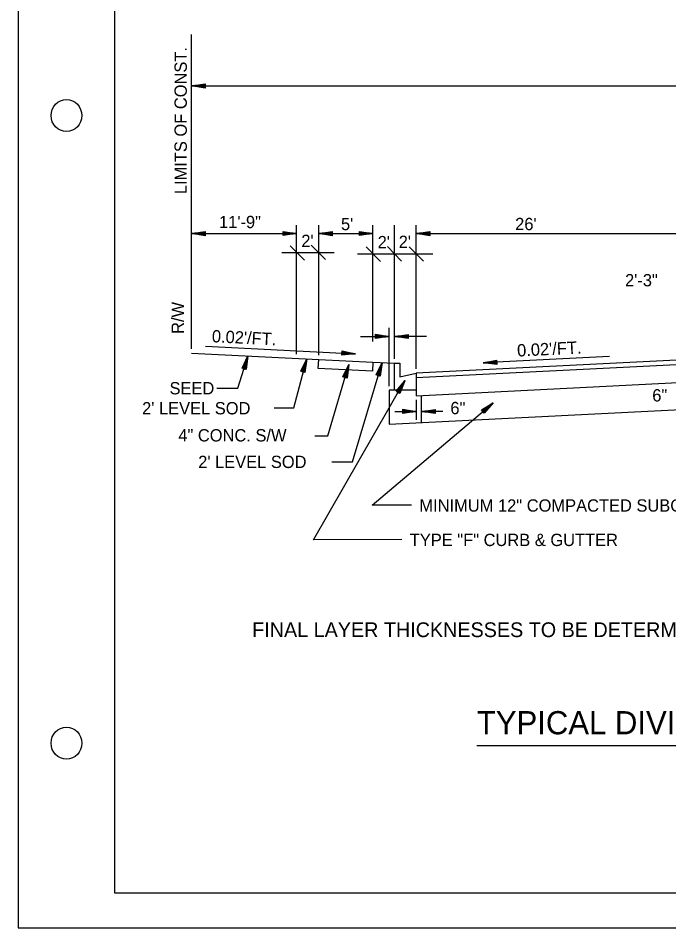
# Model space of a CAD drawing. Extents: x 29.7 to 46.4, y -39.2 to -28.2.
# Drawn here: x 29.7 to 34.11, y -39.2 to -33.04 of the extents above; entities that cross this region are included whole.
import ezdxf

# ---------------------------------------------------------------- set-up
doc = ezdxf.new("R2010")
doc.units = 0
for name, color, linetype in [('Level 1', 7, 'Continuous'), ('Level 10', 7, 'Continuous'), ('Level 4', 7, 'Continuous'), ('Level 60', 7, 'Continuous'), ('Level 8', 7, 'Continuous'), ('Level 9', 7, 'Continuous')]:
    doc.layers.add(name, color=color, linetype=linetype)

msp = doc.modelspace()

# ---------------------------------------------------------------- linework, layer by layer
at = {"layer": 'Level 4'}
msp.add_line((37.3605, -37.9659), (32.8081, -37.9659), dxfattribs=at)
at = {"layer": 'Level 60'}
for points in [[(29.7027, -39.1993), (46.0327, -39.1993), (46.0327, -28.1926), (29.7027, -28.1926)], [(30.3565, -28.4094), (45.7818, -28.4094), (45.7818, -38.965), (30.3565, -38.965)]]:
    msp.add_lwpolyline(points, close=True, dxfattribs=at)
for centre in [(30.0296, -33.6959), (30.0296, -37.9486)]:
    msp.add_ellipse(centre, major_axis=(0, 0.1083), ratio=0.96, dxfattribs=at)
at = {"layer": 'Level 8'}
for p, q in [((30.8765, -35.2762), (30.8765, -33.1461)), ((30.8765, -33.4948), (39.6765, -33.4948)), ((31.5884, -35.3118), (31.5884, -34.4376)), ((31.7381, -35.3193), (31.7381, -34.4376)), ((32.1048, -35.2277), (32.1048, -34.4376)), ((32.2515, -35.345), (32.2515, -34.4376)), ((32.3981, -35.4128), (32.3981, -34.4376)), ((30.8765, -34.4953), (31.5884, -34.4953)), ((31.7381, -34.4953), (32.1048, -34.4953)), ((32.3981, -34.4953), (34.3048, -34.4953)), ((31.6871, -34.5734), (31.7834, -34.6713)), ((31.4886, -34.6247), (31.842, -34.6247)), ((31.545, -34.5784), (31.6414, -34.6764)), ((31.9999, -34.6335), (32.5106, -34.6335)), ((32.0591, -34.5855), (32.1554, -34.6835)), ((32.2025, -34.5834), (32.2989, -34.6814)), ((32.3509, -34.5847), (32.4472, -34.6827)), ((32.0215, -35.1924), (32.2148, -35.1924)), ((32.2148, -35.5283), (32.2148, -35.1346)), ((32.4683, -35.1924), (32.2515, -35.1924)), ((30.8765, -35.3051), (31.7381, -35.3482)), ((30.9709, -35.2593), (31.9862, -35.31)), ((32.1048, -35.3665), (32.2515, -35.3739)), ((34.4331, -35.3399), (32.3981, -35.4417)), ((34.3048, -35.3776), (32.3981, -35.4729)), ((33.708, -35.3289), (32.8512, -35.3717)), ((32.3981, -35.6229), (32.3981, -35.7584)), ((32.4348, -35.7758), (32.4348, -35.5922)), ((32.2538, -35.7007), (32.3981, -35.7007)), ((32.5791, -35.7007), (32.4348, -35.7007))]:
    msp.add_line(p, q, dxfattribs=at)
for points in [[(31.0482, -35.5439), (31.1892, -35.5433), (31.2573, -35.328)], [(31.4367, -35.6762), (31.5703, -35.6762), (31.6572, -35.3441)], [(31.7381, -35.3482), (32.1048, -35.3665), (32.1018, -35.4269), (31.7351, -35.4086), (31.7381, -35.3482)], [(31.8256, -36.0421), (31.9668, -36.0421), (32.1675, -35.3698)], [(32.2515, -35.3739), (32.2881, -35.3739), (32.2881, -35.4655), (32.3981, -35.4417), (32.3981, -35.5572), (32.2515, -35.5572), (32.2515, -35.3739)], [(31.7107, -35.866), (31.8006, -35.866), (31.942, -35.3825)], [(32.2999, -36.5692), (31.7021, -36.5698), (32.3204, -35.4918)], [(32.2515, -35.5572), (32.2148, -35.5572), (32.2148, -35.7868), (34.5065, -35.6722), (34.5065, -35.4619), (34.4698, -35.4619)], [(32.3981, -35.5572), (32.3981, -35.594), (34.3048, -35.4987), (34.3048, -35.4619)], [(32.3669, -36.3359), (32.1005, -36.3359), (32.9194, -35.6418)]]:
    msp.add_lwpolyline(points, dxfattribs=at)
at = {"layer": 'Level 9'}
for p, q in [((30.968, -33.4856), (30.8765, -33.4948)), ((30.8765, -33.4948), (30.968, -33.4948)), ((30.968, -33.4994), (30.8765, -33.4948)), ((30.8765, -33.4948), (30.968, -33.5039)), ((30.968, -33.5094), (30.8766, -33.4945)), ((30.8769, -33.4942), (30.968, -33.4811)), ((30.968, -33.4902), (30.881, -33.4948)), ((30.968, -33.4811), (30.968, -33.5094)), ((30.968, -33.5039), (30.968, -33.4902)), ((30.968, -33.4948), (30.968, -33.4994)), ((30.968, -34.4862), (30.8765, -34.4953)), ((30.8765, -34.4953), (30.968, -34.4953)), ((30.968, -34.4999), (30.8765, -34.4953)), ((30.8765, -34.4953), (30.968, -34.5045)), ((30.968, -34.51), (30.8766, -34.4951)), ((30.8769, -34.4947), (30.968, -34.4816)), ((30.968, -34.4908), (30.881, -34.4953)), ((30.968, -34.4816), (30.968, -34.51)), ((30.968, -34.5045), (30.968, -34.4908)), ((30.968, -34.4953), (30.968, -34.4999)), ((31.4968, -34.509), (31.4968, -34.4807)), ((31.4968, -34.4807), (31.5883, -34.4956)), ((31.588, -34.4959), (31.4968, -34.509)), ((31.5884, -34.4953), (31.4969, -34.4862)), ((31.4969, -34.4862), (31.4969, -34.4999)), ((31.4969, -34.4953), (31.4969, -34.4908)), ((31.4969, -34.4908), (31.5884, -34.4953)), ((31.4969, -34.5045), (31.5884, -34.4953)), ((31.5884, -34.4953), (31.4969, -34.4953)), ((31.4969, -34.4999), (31.5838, -34.4953)), ((31.8296, -34.4862), (31.7381, -34.4953)), ((31.7381, -34.4953), (31.8296, -34.4953)), ((31.8296, -34.4999), (31.7381, -34.4953)), ((31.7381, -34.4953), (31.8296, -34.5045)), ((31.8297, -34.51), (31.7383, -34.4951)), ((31.7386, -34.4947), (31.8297, -34.4816)), ((31.8296, -34.4908), (31.7427, -34.4953)), ((31.8296, -34.5045), (31.8296, -34.4908)), ((31.8296, -34.4953), (31.8296, -34.4999)), ((31.8297, -34.4816), (31.8297, -34.51)), ((32.0132, -34.509), (32.0132, -34.4807)), ((32.0132, -34.4807), (32.1046, -34.4956)), ((32.1043, -34.4959), (32.0132, -34.509)), ((32.1048, -34.4953), (32.0133, -34.4862)), ((32.0133, -34.4862), (32.0133, -34.4999)), ((32.0133, -34.4953), (32.0133, -34.4908)), ((32.0133, -34.4908), (32.1048, -34.4953)), ((32.0133, -34.5045), (32.1048, -34.4953)), ((32.1048, -34.4953), (32.0133, -34.4953)), ((32.0133, -34.4999), (32.1002, -34.4953)), ((32.4896, -34.4862), (32.3981, -34.4953)), ((32.3981, -34.4953), (32.4896, -34.4953)), ((32.4896, -34.4999), (32.3981, -34.4953)), ((32.3981, -34.4953), (32.4896, -34.5045)), ((32.4897, -34.51), (32.3983, -34.4951)), ((32.3986, -34.4947), (32.4897, -34.4816)), ((32.4896, -34.4908), (32.4027, -34.4953)), ((32.4896, -34.5045), (32.4896, -34.4908)), ((32.4896, -34.4953), (32.4896, -34.4999)), ((32.4897, -34.4816), (32.4897, -34.51)), ((32.1232, -35.2061), (32.1232, -35.1777)), ((32.1232, -35.1777), (32.2146, -35.1926)), ((32.2148, -35.1924), (32.1233, -35.1832)), ((32.1233, -35.1832), (32.1233, -35.1969)), ((32.1233, -35.1924), (32.1233, -35.1878)), ((32.1233, -35.1878), (32.2148, -35.1924)), ((32.1233, -35.2015), (32.2148, -35.1924)), ((32.2148, -35.1924), (32.1233, -35.1924)), ((32.1233, -35.1969), (32.2102, -35.1924)), ((32.343, -35.1832), (32.2515, -35.1924)), ((32.2515, -35.1924), (32.343, -35.1924)), ((32.343, -35.1969), (32.2515, -35.1924)), ((32.2515, -35.1924), (32.343, -35.2015)), ((32.343, -35.207), (32.2516, -35.1921)), ((32.2519, -35.1918), (32.343, -35.1787)), ((32.343, -35.1878), (32.256, -35.1924)), ((32.343, -35.1787), (32.343, -35.207)), ((32.343, -35.2015), (32.343, -35.1878)), ((32.343, -35.1924), (32.343, -35.1969)), ((32.2143, -35.193), (32.1232, -35.2061)), ((31.8942, -35.3188), (31.8956, -35.2906)), ((31.9859, -35.3103), (31.8942, -35.3188)), ((31.8945, -35.3143), (31.9864, -35.3098)), ((31.8954, -35.2961), (31.8947, -35.3098)), ((31.8947, -35.3098), (31.9818, -35.3095)), ((31.895, -35.3052), (31.8952, -35.3006)), ((31.9864, -35.3098), (31.895, -35.3052)), ((31.8952, -35.3006), (31.9864, -35.3098)), ((31.9864, -35.3098), (31.8954, -35.2961)), ((31.8956, -35.2906), (31.9862, -35.31)), ((31.2185, -35.4082), (31.2585, -35.3246)), ((31.2583, -35.3244), (31.2238, -35.4097)), ((31.2282, -35.4109), (31.2583, -35.3244)), ((31.2583, -35.3244), (31.2326, -35.4122)), ((31.237, -35.4135), (31.257, -35.3288)), ((31.2414, -35.4148), (31.2583, -35.3244)), ((31.2587, -35.325), (31.2457, -35.4161)), ((31.6174, -35.4279), (31.6574, -35.3443)), ((31.6572, -35.3441), (31.6227, -35.4294)), ((31.6271, -35.4307), (31.6572, -35.3441)), ((31.6572, -35.3441), (31.6315, -35.4319)), ((31.6359, -35.4332), (31.6559, -35.3485)), ((31.6403, -35.4345), (31.6572, -35.3441)), ((31.6576, -35.3447), (31.6446, -35.4359)), ((32.1277, -35.4536), (32.1677, -35.37)), ((32.1675, -35.3698), (32.133, -35.455)), ((32.1374, -35.4563), (32.1675, -35.3698)), ((32.1675, -35.3698), (32.1418, -35.4576)), ((32.1462, -35.4589), (32.1662, -35.3742)), ((32.1506, -35.4602), (32.1675, -35.3698)), ((32.1679, -35.3704), (32.1549, -35.4615)), ((32.9421, -35.358), (32.8512, -35.3717)), ((32.8512, -35.3717), (32.9426, -35.3671)), ((32.9428, -35.3717), (32.8512, -35.3717)), ((32.8512, -35.3717), (32.9431, -35.3763)), ((32.9434, -35.3818), (32.8513, -35.3714)), ((32.8516, -35.3711), (32.942, -35.3535)), ((32.9424, -35.3626), (32.8558, -35.3715)), ((32.942, -35.3535), (32.9434, -35.3818)), ((32.9431, -35.3763), (32.9424, -35.3626)), ((32.9426, -35.3671), (32.9428, -35.3717)), ((31.2457, -35.4161), (31.2185, -35.4082)), ((31.2238, -35.4097), (31.237, -35.4135)), ((31.2326, -35.4122), (31.2282, -35.4109)), ((31.6446, -35.4359), (31.6174, -35.4279)), ((31.6227, -35.4294), (31.6359, -35.4332)), ((31.6315, -35.4319), (31.6271, -35.4307)), ((31.9022, -35.4663), (31.9422, -35.3827)), ((31.942, -35.3825), (31.9075, -35.4677)), ((31.9119, -35.469), (31.942, -35.3825)), ((31.942, -35.3825), (31.9163, -35.4703)), ((31.9207, -35.4716), (31.9407, -35.3869)), ((31.9251, -35.4729), (31.942, -35.3825)), ((31.9424, -35.3831), (31.9294, -35.4742)), ((31.9294, -35.4742), (31.9022, -35.4663)), ((31.9075, -35.4677), (31.9207, -35.4716)), ((31.9163, -35.4703), (31.9119, -35.469)), ((32.1549, -35.4615), (32.1277, -35.4536)), ((32.133, -35.455), (32.1462, -35.4589)), ((32.1418, -35.4576), (32.1374, -35.4563)), ((32.262, -35.5643), (32.32, -35.4921)), ((32.3199, -35.4918), (32.2669, -35.567)), ((32.2708, -35.5692), (32.3199, -35.4918)), ((32.3199, -35.4918), (32.2748, -35.5715)), ((32.2788, -35.5738), (32.3176, -35.4958)), ((32.2828, -35.576), (32.3199, -35.4918)), ((32.3202, -35.4925), (32.2867, -35.5783)), ((32.2867, -35.5783), (32.262, -35.5643)), ((32.2669, -35.567), (32.2788, -35.5738)), ((32.2748, -35.5715), (32.2708, -35.5692)), ((32.84, -35.6896), (32.9195, -35.6421)), ((32.9194, -35.6418), (32.8436, -35.6937)), ((32.8465, -35.6972), (32.9194, -35.6418)), ((32.9194, -35.6418), (32.8494, -35.7007)), ((32.8524, -35.7042), (32.9159, -35.6447)), ((32.8553, -35.7077), (32.9194, -35.6418)), ((32.9195, -35.6425), (32.8582, -35.7112)), ((32.3065, -35.7144), (32.3065, -35.6861)), ((32.3065, -35.6861), (32.398, -35.701)), ((32.3977, -35.7013), (32.3065, -35.7144)), ((32.3981, -35.7007), (32.3066, -35.6916)), ((32.3066, -35.6916), (32.3066, -35.7053)), ((32.3066, -35.7007), (32.3066, -35.6961)), ((32.3066, -35.6961), (32.3981, -35.7007)), ((32.3066, -35.7098), (32.3981, -35.7007)), ((32.3981, -35.7007), (32.3066, -35.7007)), ((32.3066, -35.7053), (32.3935, -35.7007)), ((32.5263, -35.6916), (32.4348, -35.7007)), ((32.4348, -35.7007), (32.5263, -35.7007)), ((32.5263, -35.7053), (32.4348, -35.7007)), ((32.4348, -35.7007), (32.5263, -35.7098)), ((32.5264, -35.7153), (32.4349, -35.7004)), ((32.4353, -35.7001), (32.5264, -35.687)), ((32.5263, -35.6961), (32.4394, -35.7007)), ((32.5263, -35.7098), (32.5263, -35.6961)), ((32.5263, -35.7007), (32.5263, -35.7053)), ((32.5264, -35.687), (32.5264, -35.7153)), ((32.8582, -35.7112), (32.84, -35.6896)), ((32.8436, -35.6937), (32.8524, -35.7042)), ((32.8494, -35.7007), (32.8465, -35.6972))]:
    msp.add_line(p, q, dxfattribs=at)

# ---------------------------------------------------------------- texts
at = {"layer": 'Level 1'}
msp.add_text('FINAL LAYER THICKNESSES TO BE DETERMINED BY THE ENGINEERS PAVEMENT DESIGN CALCULATIONS.', height=0.1, dxfattribs=at).set_placement((31.2874, -37.2297))
at = {"layer": 'Level 10'}
msp.add_text('TYPICAL DIVIDED ROADWAY SECTION', height=0.157302, dxfattribs=at).set_placement((32.8088, -37.8884))
at = {"layer": 'Level 8'}
for s, height, rotation, p in [('LIMITS OF CONST.', 0.083333, 90, (30.8446, -34.2283)), ('R/W', 0.08333, 90, (30.8246, -35.175)), ("0.02'/FT.", 0.08333, 357.13759, (31.0126, -35.2311)), ("0.02'/FT.", 0.08333, 2.86241, (33.0834, -35.3292))]:
    msp.add_text(s, height=height, rotation=rotation, dxfattribs=at).set_placement(p)
for s, height, p in [('11\'-9"', 0.08333, (31.0627, -34.4586)), ("5'", 0.08333, (31.8887, -34.4722)), ("26'", 0.08333, (33.0682, -34.4722)), ("2'", 0.08333, (31.6201, -34.5866)), ("2'", 0.08333, (32.1371, -34.5949)), ("2'", 0.08333, (32.2796, -34.5929)), ('2\'-3"', 0.08333, (33.8125, -34.8529)), ('SEED', 0.08333, (30.7273, -35.5848)), ('6"', 0.08333, (33.9967, -35.633)), ("2' LEVEL SOD", 0.083333, (30.5418, -35.7204)), ('6"', 0.08333, (32.6294, -35.7192)), ('4" CONC. S/W', 0.083333, (30.7869, -35.904)), ("2' LEVEL SOD", 0.083333, (30.9216, -36.0839)), ('MINIMUM 12" COMPACTED SUBGRADE', 0.083333, (32.4197, -36.3795)), ('TYPE "F" CURB & GUTTER', 0.083333, (32.3544, -36.6127))]:
    msp.add_text(s, height=height, dxfattribs=at).set_placement(p)

doc.saveas('drawing.dxf')
